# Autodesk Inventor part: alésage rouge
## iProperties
Shininess: 20.0
Length Units: 11269
Angle Units: 11279
Time Units: 11290
Mass Units: 11283
Length Display Precision: 3
Angle Display Precision: 2
Created: 2002-01
Part Number: alésage rouge
Material: Par défaut
Document SubType Name: Modélisation
Designer: Chris...
Density: 0.0
Volumn: 0.0
Area: 0.0
PropertySet Name: Model Information
Control State: 0
Master: False
Checked Out: False
Author: Chris...
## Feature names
1. Extrusion1
2. Extrusion2
